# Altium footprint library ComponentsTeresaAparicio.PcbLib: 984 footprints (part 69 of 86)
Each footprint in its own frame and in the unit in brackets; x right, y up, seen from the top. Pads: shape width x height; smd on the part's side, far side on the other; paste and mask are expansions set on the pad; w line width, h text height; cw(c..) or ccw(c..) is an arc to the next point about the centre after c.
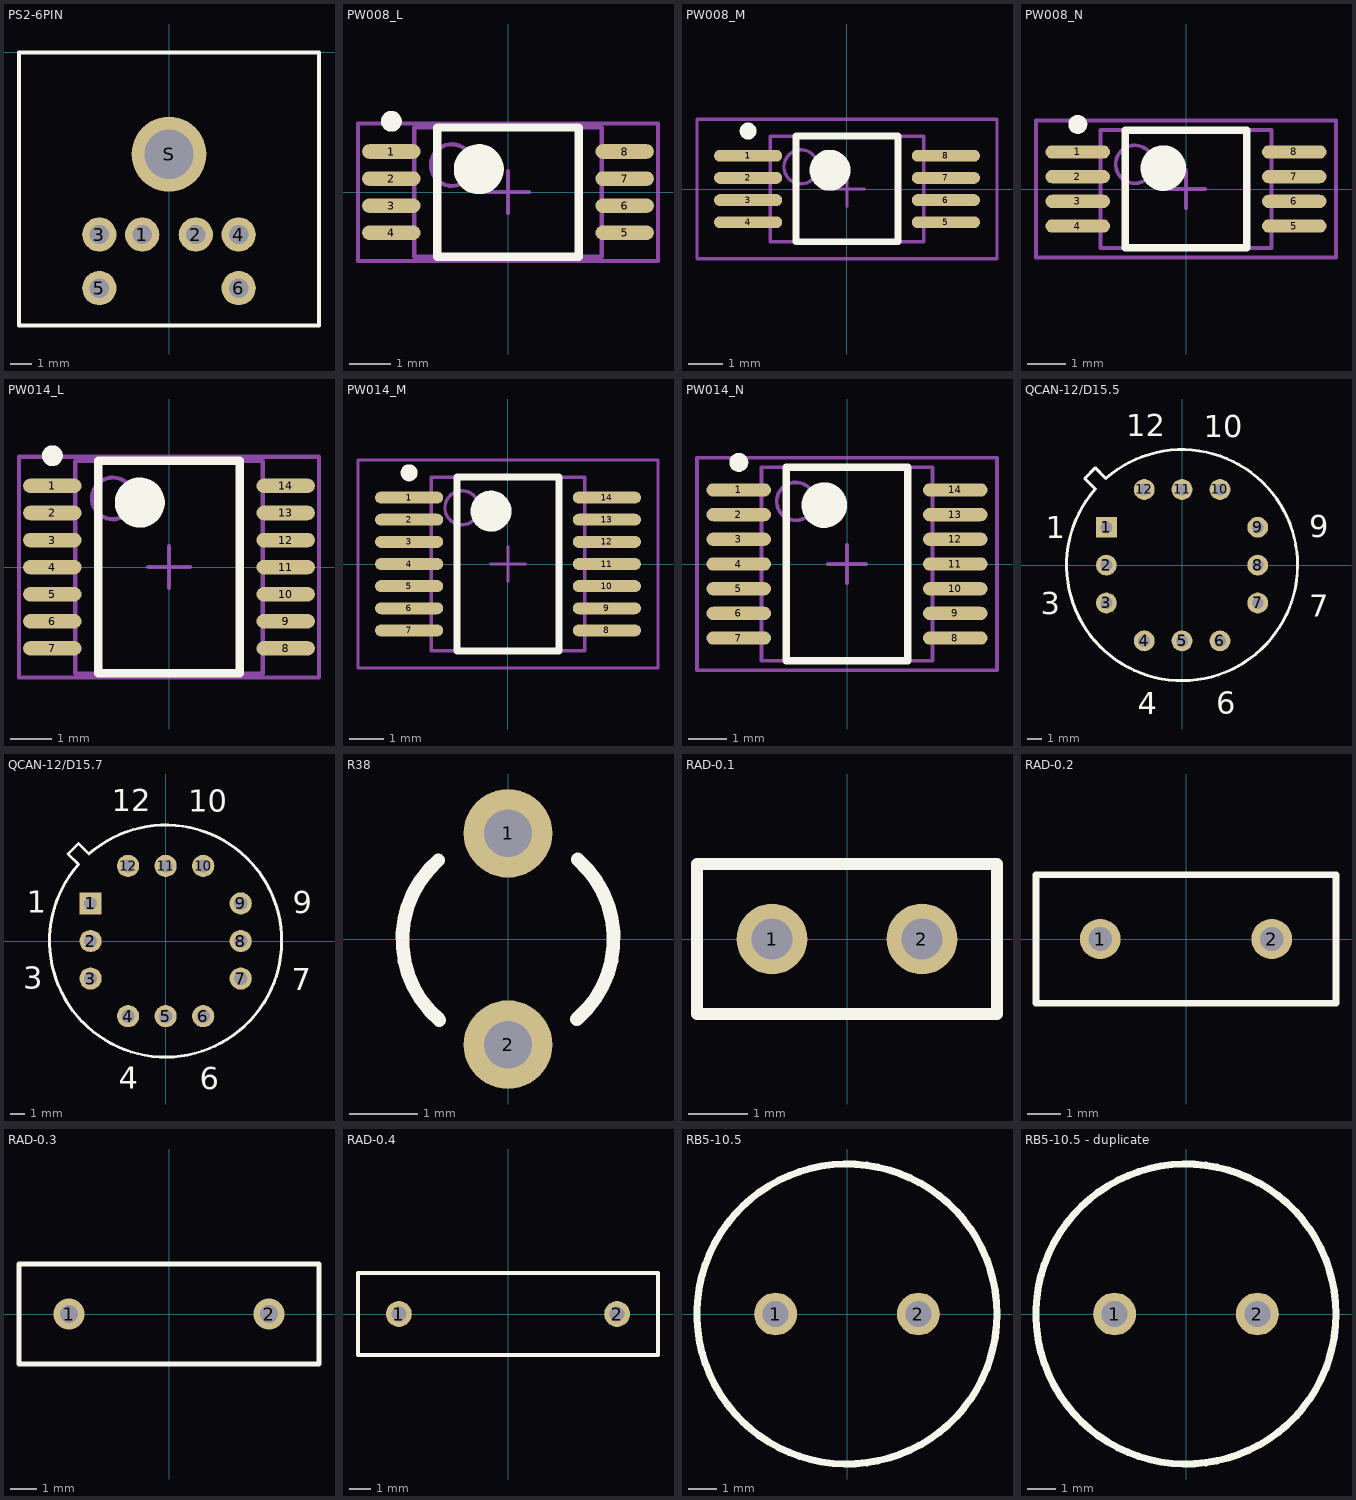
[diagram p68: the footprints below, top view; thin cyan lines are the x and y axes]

## PS2-6PIN [mm] "PS2 Socket, 6 Pin, Through Hole"
pads (7):
  round 1.6 hole 0.9: 1(-1.25,-8.5) 2(1.25,-8.5) 3(-3.25,-8.5) 4(3.25,-8.5) 5(-3.25,-11) 6(3.25,-11)
  round 3.5 hole 2.3: S(0,-4.75)
Top Overlay:
  lines w0.2: -7,-12.75 -7,0 7,0 7,-12.75 -7,-12.75

## PW008_L [mm] "SOP, 8-Leads, Body 3x4.4mm, Pitch 0.65mm, IPC High Density"
height 3.1
pads (8):
  oval 1.4x0.35 smd: 1(-2.8,0.975) 2(-2.8,0.325) 3(-2.8,-0.325) 4(-2.8,-0.975) 5(2.8,-0.975) 6(2.8,-0.325) 7(2.8,0.325) 8(2.8,0.975)
Top Overlay:
  circle w0.25: c-2.8,1.7 r0.125
  circle w0.6: c-0.7,0.55 r0.3
  lines w0.2: -1.7,-1.55 -1.7,1.55 1.7,1.55 1.7,-1.55 -1.7,-1.55
Mechanical 13:
  circle w0.1: c-1.35,0.65 r0.5
  lines w0.1: -2.25,-1.55 -2.25,1.55 2.25,1.55 2.25,-1.55 -2.25,-1.55
Mechanical 15:
  lines w0.1: -0.5,0 0.5,0 ; 0,-0.5 0,0.5 ; -3.6,-1.65 -3.6,1.65 3.6,1.65 3.6,-1.65 -3.6,-1.65
3D body: height 3.1, standoff 0, extent -2.25,-1.55 2.25,1.55

## PW008_M [mm] "SOP, 8-Leads, Body 3x4.4mm, Pitch 0.65mm, IPC Low Density"
height 3.1
pads (8):
  oval 2x0.35 smd: 1(-2.9,0.975) 2(-2.9,0.325) 3(-2.9,-0.325) 4(-2.9,-0.975) 5(2.9,-0.975) 6(2.9,-0.325) 7(2.9,0.325) 8(2.9,0.975)
Top Overlay:
  circle w0.6: c-0.5,0.55 r0.3
  circle w0.25: c-2.9,1.7 r0.125
  lines w0.2: -1.5,-1.55 1.5,-1.55 1.5,1.55 -1.5,1.55 -1.5,-1.55
Mechanical 13:
  circle w0.1: c-1.35,0.65 r0.5
  lines w0.1: -2.25,-1.55 2.25,-1.55 2.25,1.55 -2.25,1.55 -2.25,-1.55
Mechanical 15:
  lines w0.1: -0.5,0 0.5,0 ; 0,-0.5 0,0.5 ; -4.4,-2.05 4.4,-2.05 4.4,2.05 -4.4,2.05 -4.4,-2.05
3D body: height 3.1, standoff 0, extent -2.25,-1.55 2.25,1.55

## PW008_N [mm] "SOP, 8-Leads, Body 3x4.4mm, Pitch 0.65mm, IPC Medium Density"
height 3.1
pads (8):
  oval 1.7x0.35 smd: 1(-2.85,0.975) 2(-2.85,0.325) 3(-2.85,-0.325) 4(-2.85,-0.975) 5(2.85,-0.975) 6(2.85,-0.325) 7(2.85,0.325) 8(2.85,0.975)
Top Overlay:
  circle w0.6: c-0.6,0.55 r0.3
  circle w0.25: c-2.85,1.7 r0.125
  lines w0.2: -1.6,-1.55 1.6,-1.55 1.6,1.55 -1.6,1.55 -1.6,-1.55
Mechanical 13:
  circle w0.1: c-1.35,0.65 r0.5
  lines w0.1: -2.25,-1.55 2.25,-1.55 2.25,1.55 -2.25,1.55 -2.25,-1.55
Mechanical 15:
  lines w0.1: -0.5,0 0.5,0 ; 0,-0.5 0,0.5 ; -3.95,-1.8 3.95,-1.8 3.95,1.8 -3.95,1.8 -3.95,-1.8
3D body: height 3.1, standoff 0, extent -2.25,-1.55 2.25,1.55

## PW014_L [mm] "TSOP, 14-Leads, Body 5x4.4mm, Pitch 0.65mm, IPC High Density"
height 1.2
pads (14):
  oval 1.4x0.35 smd: 1(-2.8,1.95) 2(-2.8,1.3) 3(-2.8,0.65) 4(-2.8,0) 5(-2.8,-0.65) 6(-2.8,-1.3) 7(-2.8,-1.95) 8(2.8,-1.95) 9(2.8,-1.3) 10(2.8,-0.65) 11(2.8,0) 12(2.8,0.65) 13(2.8,1.3) 14(2.8,1.95)
Top Overlay:
  circle w0.6: c-0.7,1.55 r0.3
  circle w0.25: c-2.8,2.675 r0.125
  lines w0.2: -1.7,-2.55 1.7,-2.55 1.7,2.55 -1.7,2.55 -1.7,-2.55
Mechanical 13:
  circle w0.1: c-1.35,1.65 r0.5
  lines w0.1: -2.25,-2.55 2.25,-2.55 2.25,2.55 -2.25,2.55 -2.25,-2.55
Mechanical 15:
  lines w0.1: -0.5,0 0.5,0 ; 0,-0.5 0,0.5 ; -3.6,-2.65 3.6,-2.65 3.6,2.65 -3.6,2.65 -3.6,-2.65
3D body: height 1.2, standoff 0, extent -2.25,-2.55 2.25,2.55

## PW014_M [mm] "TSOP, 14-Leads, Body 5x4.4mm, Pitch 0.65mm, IPC Low Density"
height 1.2
pads (14):
  oval 2x0.35 smd: 1(-2.9,1.95) 2(-2.9,1.3) 3(-2.9,0.65) 4(-2.9,0) 5(-2.9,-0.65) 6(-2.9,-1.3) 7(-2.9,-1.95) 8(2.9,-1.95) 9(2.9,-1.3) 10(2.9,-0.65) 11(2.9,0) 12(2.9,0.65) 13(2.9,1.3) 14(2.9,1.95)
Top Overlay:
  circle w0.25: c-2.9,2.675 r0.125
  circle w0.6: c-0.5,1.55 r0.3
  lines w0.2: -1.5,-2.55 -1.5,2.55 1.5,2.55 1.5,-2.55 -1.5,-2.55
Mechanical 13:
  circle w0.1: c-1.35,1.65 r0.5
  lines w0.1: -2.25,-2.55 -2.25,2.55 2.25,2.55 2.25,-2.55 -2.25,-2.55
Mechanical 15:
  lines w0.1: -0.5,0 0.5,0 ; 0,-0.5 0,0.5 ; -4.4,-3.05 -4.4,3.05 4.4,3.05 4.4,-3.05 -4.4,-3.05
3D body: height 1.2, standoff 0, extent -2.25,-2.55 2.25,2.55

## PW014_N [mm] "TSOP, 14-Leads, Body 5x4.4mm, Pitch 0.65mm, IPC Medium Density"
height 1.2
pads (14):
  oval 1.7x0.35 smd: 1(-2.85,1.95) 2(-2.85,1.3) 3(-2.85,0.65) 4(-2.85,0) 5(-2.85,-0.65) 6(-2.85,-1.3) 7(-2.85,-1.95) 8(2.85,-1.95) 9(2.85,-1.3) 10(2.85,-0.65) 11(2.85,0) 12(2.85,0.65) 13(2.85,1.3) 14(2.85,1.95)
Top Overlay:
  circle w0.25: c-2.85,2.675 r0.125
  circle w0.6: c-0.6,1.55 r0.3
  lines w0.2: -1.6,-2.55 -1.6,2.55 1.6,2.55 1.6,-2.55 -1.6,-2.55
Mechanical 13:
  circle w0.1: c-1.35,1.65 r0.5
  lines w0.1: -2.25,-2.55 -2.25,2.55 2.25,2.55 2.25,-2.55 -2.25,-2.55
Mechanical 15:
  lines w0.1: -0.5,0 0.5,0 ; 0,-0.5 0,0.5 ; -3.95,-2.8 -3.95,2.8 3.95,2.8 3.95,-2.8 -3.95,-2.8
3D body: height 1.2, standoff 0, extent -2.25,-2.55 2.25,2.55

## QCAN-12/D15.5 [mm] "Can; 12 Leads; 10.16 mm Square Array; Lead Dia. 0.48 mm (max)"
height 3.81
pads (12):
  rect 1.4x1.4 hole 0.8: 1(-5.08,2.54)
  round 1.4 hole 0.8: 2(-5.08,0) 3(-5.08,-2.54) 4(-2.54,-5.08) 5(0,-5.08) 6(2.54,-5.08) 7(5.08,-2.54) 8(5.08,0) 9(5.08,2.54) 10(2.54,5.08) 11(0,5.08) 12(-2.54,5.08)
Top Overlay:
  lines w0.2: -6.529,5.822 -5.822,5.115 ccw(c0,0) -5.115,5.822 -5.822,6.529 -6.529,5.822
  text "12" at -3.754,8.642 h1.5
  text "10" at 1.446,8.583 h1.5
  text "9" at 8.519,1.867 h1.5
  text "7" at 8.519,-3.453 h1.5
  text "6" at 2.278,-9.96 h1.5
  text "4" at -2.982,-9.99 h1.5
  text "3" at -9.49,-3.304 h1.5
  text "1" at -9.16,1.808 h1.5

## QCAN-12/D15.7 [mm] "Can; 12 Leads; 10.16 mm Square Array; Lead Dia. 0.53 mm (max)"
height 4.6
pads (12):
  rect 1.5x1.5 hole 0.9: 1(-5.08,2.54)
  round 1.5 hole 0.9: 2(-5.08,0) 3(-5.08,-2.54) 4(-2.54,-5.08) 5(0,-5.08) 6(2.54,-5.08) 7(5.08,-2.54) 8(5.08,0) 9(5.08,2.54) 10(2.54,5.08) 11(0,5.08) 12(-2.54,5.08)
Top Overlay:
  lines w0.2: -6.6,5.893 -5.893,6.6 -5.186,5.893 cw(c0,0) -5.893,5.186 -6.6,5.893
  text "1" at -9.398,1.916 h1.5
  text "3" at -9.639,-3.231 h1.5
  text "4" at -3.169,-9.979 h1.5
  text "6" at 2.298,-10.009 h1.5
  text "7" at 8.534,-3.321 h1.5
  text "9" at 8.594,1.886 h1.5
  text "10" at 1.525,8.76 h1.5
  text "12" at -3.64,8.782 h1.5

## R38 [mm] "Crystal, Thru-Hole; 2 Leads; Body 3.1 x 8.2 mm (Dia.xH)"
height 8.2
pads (2):
  round 1.3 hole 0.7: 1(0,1.55) 2(0,-1.55)
Top Overlay:
  lines w0.2: -1.022,1.155 ccw(c0,-0.01) -1.006,-1.189 ; 1.006,-1.179 ccw(c0,0) 1.022,1.165

## RAD-0.1 [mm] "Radial Cap, Thru-Hole; 2 Leads; 0.1 in Pin Spacing"
pads (2):
  round 1.2 hole 0.7: 1(-1.27,0) 2(1.27,0)
Top Overlay:
  lines w0.2: -2.54,-1.27 -2.54,1.27 2.54,1.27 2.54,-1.27 -2.54,-1.27

## RAD-0.2 [mm] "Radial Cap, Thru-Hole; 2 Leads; 0.2 in Pin Spacing"
pads (2):
  round 1.2 hole 0.7: 1(-2.54,0) 2(2.54,0)
Top Overlay:
  lines w0.2: -4.445,-1.905 4.445,-1.905 4.445,1.905 -4.445,1.905 -4.445,-1.905

## RAD-0.3 [mm] "Radial Cap, Thru-Hole; 2 Leads; 0.3 in Pin Spacing"
height 6
pads (2):
  round 1.2 hole 0.7: 1(-3.81,0) 2(3.81,0)
Top Overlay:
  lines w0.2: -5.715,-1.905 5.715,-1.905 5.715,1.905 -5.715,1.905 -5.715,-1.905

## RAD-0.4 [mm] "Radial Cap, Thru-Hole; 2 Leads; 0.4 in Pin Spacing"
pads (2):
  round 1.2 hole 0.7: 1(-5.08,0) 2(5.08,0)
Top Overlay:
  lines w0.2: -6.985,-1.905 -6.985,1.905 6.985,1.905 6.985,-1.905 -6.985,-1.905

## RB5-10.5 [mm] "Capacitor (Radial); 2 Leads"
pads (2):
  round 1.5 hole 0.9: 1(-2.5,0) 2(2.5,0)
Top Overlay:
  circle w0.25: c0,0 r5.25
Mechanical 1:
  circle w0.02: c0,0 r5.25

## RB5-10.5 - duplicate [mm] "Capacitor (Radial); 2 Leads"
pads (2):
  round 1.5 hole 0.9: 1(-2.5,0) 2(2.5,0)
Top Overlay:
  circle w0.25: c0,0 r5.25
Mechanical 1:
  circle w0.02: c0,0 r5.25
3D body: height 15.04, standoff -14.46, extent -5,-5.08 5,4.92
